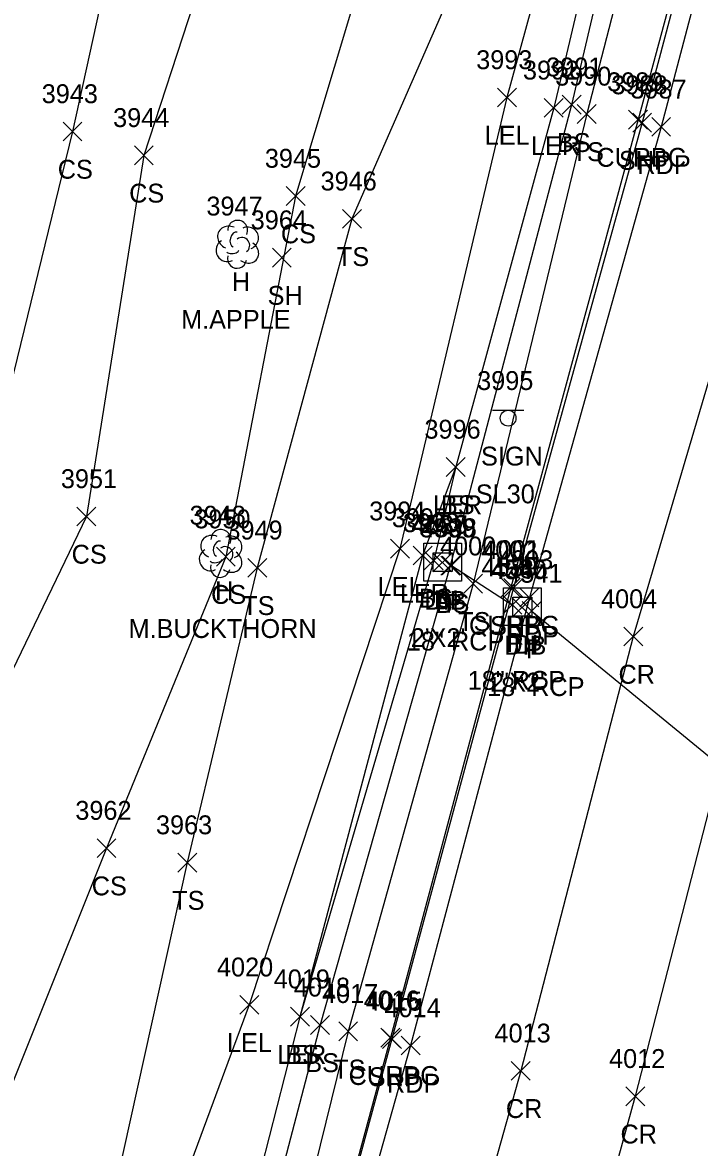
# Model space of a CAD drawing. Extents: x 1462089 to 1464015, y 730534 to 736144.
# Drawn here: x 1462743.8 to 1462815.5, y 732128.7 to 732247.8 of the extents above; entities that cross this region are included whole.
import ezdxf

# ---------------------------------------------------------------- set-up
doc = ezdxf.new("R2010")
doc.units = 0
for name, color, linetype in [('D_A', 7, 'Continuous'), ('D_C', 7, 'Continuous'), ('D_I', 7, 'Continuous'), ('D_TIC', 7, 'Continuous'), ('DCP', 7, 'Continuous'), ('DS', 7, 'Continuous'), ('L_A', 7, 'Continuous'), ('L_C', 7, 'Continuous'), ('L_I', 7, 'Continuous'), ('L_TIC', 7, 'Continuous'), ('LARO', 7, 'Continuous'), ('LELB', 7, 'Continuous'), ('LTD', 7, 'Continuous'), ('P_A', 7, 'Continuous'), ('P_I', 7, 'Continuous'), ('P_TIC', 7, 'Continuous'), ('PET', 7, 'Continuous'), ('PRC', 7, 'Continuous'), ('PSP', 7, 'Continuous'), ('R_A', 7, 'Continuous'), ('R_I', 7, 'Continuous'), ('R_TIC', 7, 'Continuous'), ('RC', 7, 'Continuous'), ('S_A', 7, 'Continuous'), ('S_C', 7, 'Continuous'), ('S_I', 7, 'Continuous'), ('SSGN', 7, 'Continuous')]:
    doc.layers.add(name, color=color, linetype=linetype)

msp = doc.modelspace()

# ---------------------------------------------------------------- linework, layer by layer
at = {"layer": 'D_TIC'}
for points in [[(1462787.24, 732189.65), (1462789.24, 732191.65)], [(1462789.24, 732189.65), (1462787.24, 732191.65)], [(1462788.21, 732189.33), (1462790.21, 732191.33)], [(1462790.21, 732189.33), (1462788.21, 732191.33)], [(1462794.65, 732185.17), (1462796.65, 732187.17)], [(1462796.65, 732185.17), (1462794.65, 732187.17)], [(1462795.69, 732184.89), (1462797.69, 732186.89)], [(1462797.69, 732184.89), (1462795.69, 732186.89)], [(1462796.71, 732184.51), (1462798.71, 732186.51)], [(1462798.71, 732184.51), (1462796.71, 732186.51)]]:
    msp.add_lwpolyline(points, dxfattribs=at)
at = {"layer": 'DCP'}
for points in [[(1462789.21, 732190.33), (1462795.65, 732186.17)], [(1462797.71, 732185.51), (1462855.72, 732137.95)]]:
    msp.add_lwpolyline(points, dxfattribs=at)
at = {"layer": 'DS'}
for p, q in [((1462786.29, 732192.69), (1462790.29, 732192.69)), ((1462786.29, 732188.69), (1462786.29, 732192.69)), ((1462790.29, 732192.69), (1462790.29, 732188.69)), ((1462787.29, 732189.69), (1462787.29, 732191.69)), ((1462787.29, 732191.69), (1462789.29, 732191.69)), ((1462789.29, 732191.69), (1462789.29, 732189.69)), ((1462789.29, 732189.69), (1462787.29, 732189.69)), ((1462788.3, 732190.69), (1462788.3, 732190.69)), ((1462788.3, 732190.69), (1462788.3, 732190.69)), ((1462790.29, 732188.69), (1462786.29, 732188.69)), ((1462794.72, 732187.98), (1462798.72, 732187.98)), ((1462794.72, 732183.98), (1462794.72, 732187.98)), ((1462798.72, 732187.98), (1462798.72, 732183.98)), ((1462795.72, 732184.98), (1462795.72, 732186.98)), ((1462795.72, 732186.98), (1462797.72, 732186.98)), ((1462797.72, 732186.98), (1462797.72, 732184.98)), ((1462797.72, 732184.98), (1462795.72, 732184.98)), ((1462796.72, 732185.98), (1462796.72, 732185.98)), ((1462796.72, 732185.98), (1462796.72, 732185.98)), ((1462798.72, 732183.98), (1462794.72, 732183.98))]:
    msp.add_line(p, q, dxfattribs=at)
at = {"layer": 'L_TIC'}
for points in [[(1462794.09, 732238.9), (1462796.09, 732240.9)], [(1462796.09, 732238.9), (1462794.09, 732240.9)], [(1462799.04, 732237.8), (1462801.04, 732239.8)], [(1462801.04, 732237.8), (1462799.04, 732239.8)], [(1462800.93, 732238.13), (1462802.93, 732240.13)], [(1462802.93, 732238.13), (1462800.93, 732240.13)], [(1462802.53, 732237.16), (1462804.53, 732239.16)], [(1462804.53, 732237.16), (1462802.53, 732239.16)], [(1462748.08, 732235.3), (1462750.08, 732237.3)], [(1462750.08, 732235.3), (1462748.08, 732237.3)], [(1462755.64, 732232.77), (1462757.64, 732234.77)], [(1462757.64, 732232.77), (1462755.64, 732234.77)], [(1462771.71, 732228.46), (1462773.71, 732230.46)], [(1462773.71, 732228.46), (1462771.71, 732230.46)], [(1462777.67, 732226.05), (1462779.67, 732228.05)], [(1462779.67, 732226.05), (1462777.67, 732228.05)], [(1462770.25, 732221.94), (1462772.25, 732223.94)], [(1462772.25, 732221.94), (1462770.25, 732223.94)], [(1462788.66, 732199.77), (1462790.66, 732201.77)], [(1462790.66, 732199.77), (1462788.66, 732201.77)], [(1462788.66, 732199.77), (1462790.66, 732201.77)], [(1462790.66, 732199.77), (1462788.66, 732201.77)], [(1462749.55, 732194.53), (1462751.55, 732196.53)], [(1462751.55, 732194.53), (1462749.55, 732196.53)], [(1462764.32, 732190.27), (1462766.32, 732192.27)], [(1462766.32, 732190.27), (1462764.32, 732192.27)], [(1462782.76, 732191.11), (1462784.76, 732193.11)], [(1462784.76, 732191.11), (1462782.76, 732193.11)], [(1462785.16, 732190.39), (1462787.16, 732192.39)], [(1462787.16, 732190.39), (1462785.16, 732192.39)], [(1462767.65, 732189.09), (1462769.65, 732191.09)], [(1462769.65, 732189.09), (1462767.65, 732191.09)], [(1462786.33, 732189.87), (1462788.33, 732191.87)], [(1462788.33, 732189.87), (1462786.33, 732191.87)], [(1462788.09, 732189.31), (1462790.09, 732191.31)], [(1462790.09, 732189.31), (1462788.09, 732191.31)], [(1462790.51, 732187.4), (1462792.51, 732189.4)], [(1462792.51, 732187.4), (1462790.51, 732189.4)], [(1462751.68, 732159.4), (1462753.68, 732161.4)], [(1462753.68, 732159.4), (1462751.68, 732161.4)], [(1462760.23, 732157.87), (1462762.23, 732159.87)], [(1462762.23, 732157.87), (1462760.23, 732159.87)], [(1462766.8, 732142.81), (1462768.8, 732144.81)], [(1462768.8, 732142.81), (1462766.8, 732144.81)], [(1462772.17, 732141.55), (1462774.17, 732143.55)], [(1462774.17, 732141.55), (1462772.17, 732143.55)], [(1462772.17, 732141.55), (1462774.17, 732143.55)], [(1462774.17, 732141.55), (1462772.17, 732143.55)], [(1462774.29, 732140.68), (1462776.29, 732142.68)], [(1462776.29, 732140.68), (1462774.29, 732142.68)], [(1462777.27, 732140), (1462779.27, 732142)], [(1462779.27, 732140), (1462777.27, 732142)]]:
    msp.add_lwpolyline(points, dxfattribs=at)
at = {"layer": 'LARO'}
for points in [[(1462811.69, 732286.33), (1462807.23, 732269.21), (1462800.04, 732238.8), (1462789.66, 732200.77), (1462786.16, 732191.39), (1462773.17, 732142.55), (1462762.59, 732101.23), (1462750.3, 732056), (1462737.3, 732015), (1462731, 731998.27), (1462722.22, 731986.67), (1462712.54, 731977.49), (1462705.64, 731972.39), (1462692.98, 731969.55), (1462682.24, 731971.77), (1462644.49, 731992.53), (1462610.27, 732008.8), (1462590.7, 732019.88), (1462573.65, 732029.77), (1462532.93, 732051.27)], [(1462803.18, 732269.5), (1462795.09, 732239.9), (1462783.76, 732192.11), (1462767.8, 732143.81), (1462756.83, 732114.21)]]:
    msp.add_lwpolyline(points, dxfattribs=at)
at = {"layer": 'LELB'}
for points in [[(1462595.72, 732406.28), (1462619.4, 732406.7), (1462642.47, 732399.16), (1462667.34, 732396.48), (1462684.1, 732390.5), (1462719.43, 732377.7), (1462729.06, 732369.99), (1462742.49, 732352.09), (1462751.14, 732333.71), (1462745.11, 732312.38), (1462751.49, 732301.01), (1462756.6, 732270.55), (1462749.08, 732236.3), (1462739.5, 732197.27), (1462722.63, 732167.04), (1462705.2, 732121.69), (1462689.78, 732084.32), (1462690.84, 732066.26), (1462684.58, 732060.84), (1462690.56, 732032.44), (1462672.45, 732001.12)], [(1462771.34, 732370.93), (1462788.66, 732351.07), (1462799.07, 732328.54), (1462799.45, 732312.22), (1462793.43, 732294.03), (1462783.04, 732263.92), (1462772.71, 732229.46), (1462765.32, 732191.27), (1462752.68, 732160.4), (1462737.05, 732121.41), (1462720.38, 732070.54)], [(1462809.03, 732269.42), (1462801.93, 732239.13), (1462789.09, 732190.31), (1462775.29, 732141.68), (1462764.64, 732100.96), (1462752.8, 732054.52), (1462739.45, 732014.67), (1462736.17, 731994.63), (1462725.05, 731984.73), (1462716.42, 731972.55), (1462714.31, 731971.44), (1462707, 731968.07), (1462693.67, 731964.39), (1462682.54, 731969.03), (1462671.27, 731974.63), (1462642.39, 731988.79), (1462608.32, 732006.27), (1462574.67, 732024.46), (1462532.58, 732048.41)], [(1462811.59, 732269.3), (1462803.53, 732238.16), (1462791.51, 732188.4), (1462778.27, 732141), (1462768.17, 732100), (1462755.7, 732053.53), (1462741.93, 732013.79), (1462736.19, 731994.54), (1462729.1, 731982.21), (1462724.09, 731974.33), (1462718.35, 731969.42), (1462708.44, 731965.38), (1462694.1, 731962.02), (1462681.52, 731966.68), (1462670.39, 731971.8), (1462640.52, 731985.68), (1462606.11, 732003.49), (1462571.9, 732022.04), (1462531.1, 732045.76)], [(1462767.14, 732265.98), (1462756.64, 732233.77), (1462750.55, 732195.53), (1462735.33, 732163.92), (1462718.25, 732117.57), (1462704.07, 732078.38), (1462702.9, 732059.56), (1462704.25, 732052.77), (1462706.69, 732013.72), (1462698.3, 731996.47), (1462698.4, 731977.76), (1462688.47, 731989.05), (1462672.45, 732001.12), (1462653.69, 732006.74), (1462640.58, 732015.14), (1462615.76, 732028.36), (1462597.06, 732039.34), (1462574.7, 732044.02), (1462549.99, 732062.33), (1462528.92, 732079.24)], [(1462793.48, 732260.93), (1462778.67, 732227.05), (1462768.65, 732190.09), (1462761.23, 732158.87), (1462752.18, 732117.99), (1462746.45, 732098.92), (1462740.89, 732072.95), (1462731.75, 732044.77), (1462721.66, 732011.52), (1462713.9, 731990.4), (1462707.85, 731982.77)], [(1462789.66, 732200.77), (1462787.33, 732190.87), (1462773.17, 732142.55)]]:
    msp.add_lwpolyline(points, dxfattribs=at)
at = {"layer": 'LTD'}
for p, q in [((1462766.52, 732224.4), (1462766.52, 732224.4)), ((1462766.52, 732224.4), (1462766.52, 732224.4)), ((1462764.74, 732191.66), (1462764.74, 732191.66)), ((1462764.74, 732191.66), (1462764.74, 732191.66))]:
    msp.add_line(p, q, dxfattribs=at)
for centre in [(1462766.57, 732225.84), (1462764.79, 732193.1)]:
    msp.add_arc(centre, 1.05, 335.5272, 180.9563, dxfattribs=at)
for centre, major_axis, ratio, start_param, end_param in [((1462765.73, 732225.07), (1.21, -0.51), 0.895232, 1.570796, 4.712389), ((1462766.31, 732224.86), (-0.208, -0.792), 0.645439, 3.141593, 6.283185), ((1462767.56, 732224.99), (-1.14, -0.48), 0.949671, 1.570796, 4.712389), ((1462765.44, 732223.69), (0.58, -1.04), 0.959034, 3.141593, 6.283185), ((1462767.02, 732224.24), (-0.5, 0.667), 0.989748, 3.141593, 6.283185), ((1462767.52, 732223.57), (-1.09, 0.79), 0.841452, 1.570796, 4.712389), ((1462766.52, 732222.9), (0.26, 1.06), 0.942809, 1.570796, 4.712389), ((1462766.06, 732223.65), (-0.625, -0.083), 0.423636, 0, 3.141593), ((1462763.95, 732192.33), (1.21, -0.51), 0.895232, 1.570796, 4.712389), ((1462765.79, 732192.25), (-1.14, -0.48), 0.949671, 1.570796, 4.712389), ((1462763.66, 732190.95), (0.58, -1.04), 0.959034, 3.141593, 6.283185), ((1462764.54, 732192.12), (-0.208, -0.792), 0.645439, 3.141593, 6.283185), ((1462765.24, 732191.5), (-0.5, 0.667), 0.989748, 3.141593, 6.283185), ((1462764.29, 732190.91), (-0.625, -0.083), 0.423636, 0, 3.141593), ((1462765.74, 732190.83), (-1.09, 0.79), 0.841452, 1.570796, 4.712389), ((1462764.74, 732190.16), (0.26, 1.06), 0.942809, 1.570796, 4.712389)]:
    msp.add_ellipse(centre, major_axis=major_axis, ratio=ratio, start_param=start_param, end_param=end_param, dxfattribs=at)
at = {"layer": 'P_TIC'}
for points in [[(1462808.4, 732236.24), (1462810.4, 732238.24)], [(1462810.4, 732236.24), (1462808.4, 732238.24)], [(1462810.42, 732235.79), (1462812.42, 732237.79)], [(1462812.42, 732235.79), (1462810.42, 732237.79)], [(1462794.77, 732186.97), (1462796.77, 732188.97)], [(1462796.77, 732186.97), (1462794.77, 732188.97)], [(1462796.46, 732185.94), (1462798.46, 732187.94)], [(1462798.46, 732185.94), (1462796.46, 732187.94)], [(1462807.46, 732181.81), (1462809.46, 732183.81)], [(1462809.46, 732181.81), (1462807.46, 732183.81)], [(1462781.91, 732139.19), (1462783.91, 732141.19)], [(1462783.91, 732139.19), (1462781.91, 732141.19)], [(1462783.89, 732138.5), (1462785.89, 732140.5)], [(1462785.89, 732138.5), (1462783.89, 732140.5)], [(1462795.54, 732135.82), (1462797.54, 732137.82)], [(1462797.54, 732135.82), (1462795.54, 732137.82)], [(1462807.67, 732133.12), (1462809.67, 732135.12)], [(1462809.67, 732133.12), (1462807.67, 732135.12)]]:
    msp.add_lwpolyline(points, dxfattribs=at)
at = {"layer": 'PET'}
msp.add_lwpolyline([(1462974.36, 732735), (1462957.21, 732680.82), (1462945.36, 732643.96), (1462932.51, 732601.63), (1462920.15, 732563.11), (1462911.43, 732534.97), (1462898.01, 732492.33), (1462884.52, 732450), (1462822.42, 732278.6), (1462811.42, 732236.79), (1462797.46, 732186.94), (1462784.89, 732139.5), (1462773.38, 732098.59), (1462761.09, 732052.78), (1462749.31, 732009.82), (1462737.3, 731963.43), (1462717.1, 731889.53)], dxfattribs=at)
at = {"layer": 'PRC'}
for points in [[(1462985.72, 732731.93), (1462969.44, 732677.27), (1462957.49, 732641.21), (1462943.9, 732597.67), (1462931.65, 732559.61), (1462922.76, 732531.12), (1462910.18, 732489.03), (1462895.07, 732444.4), (1462885.16, 732408.13), (1462864.59, 732375.33), (1462853.42, 732347.26), (1462832.87, 732276.65), (1462823.23, 732232.91), (1462808.46, 732182.81), (1462796.54, 732136.82), (1462784.67, 732094.48), (1462773.76, 732052.9), (1462761.07, 732007.23), (1462748.95, 731961.52), (1462736.51, 731921.31)], [(1462885.16, 732408.13), (1462873.49, 732369.25), (1462865.09, 732342.58), (1462846.12, 732273.83), (1462834.44, 732229.42), (1462820.22, 732178.99), (1462808.67, 732134.12), (1462796.38, 732089.42), (1462785.55, 732047.77), (1462772.99, 732002.51), (1462761.02, 731958.42), (1462747.81, 731917.01)]]:
    msp.add_lwpolyline(points, dxfattribs=at)
at = {"layer": 'PSP'}
msp.add_lwpolyline([(1462968.73, 732736.5), (1462951.61, 732681.88), (1462940.59, 732646.44), (1462927.05, 732603.06), (1462915.13, 732564.78), (1462905.93, 732535.59), (1462892.76, 732493.15), (1462882.84, 732461.98), (1462878.84, 732452.24), (1462860.17, 732402.54), (1462855.98, 732390.47), (1462851.6, 732378.35), (1462831.73, 732320.54), (1462820.54, 732279.17), (1462809.4, 732237.24), (1462795.77, 732187.97), (1462782.91, 732140.19), (1462771.75, 732099.01), (1462759.21, 732053.14), (1462747.62, 732010.5), (1462744.84, 731999.27), (1462735.88, 731965.54), (1462724.35, 731923.62)], dxfattribs=at)
at = {"layer": 'R_TIC'}
for points in [[(1462807.97, 732236.56), (1462809.97, 732238.56)], [(1462809.97, 732236.56), (1462807.97, 732238.56)], [(1462794.49, 732187.01), (1462796.49, 732189.01)], [(1462796.49, 732187.01), (1462794.49, 732189.01)], [(1462781.74, 732139.32), (1462783.74, 732141.32)], [(1462783.74, 732139.32), (1462781.74, 732141.32)]]:
    msp.add_lwpolyline(points, dxfattribs=at)
at = {"layer": 'RC'}
msp.add_lwpolyline([(1462829.93, 732355.37), (1462830.59, 732355.49), (1462831.24, 732353.27), (1462834.24, 732341.28), (1462833.71, 732330.4), (1462831.71, 732320.54), (1462820.1, 732278.81), (1462808.97, 732237.56), (1462795.49, 732188.01), (1462782.74, 732140.32), (1462771.63, 732099.14), (1462759.13, 732053.25), (1462747.5, 732010.47), (1462744.54, 731999.36), (1462742.28, 731993.46), (1462735.21, 731981.65), (1462730.48, 731976.35), (1462728.98, 731974.4)], dxfattribs=at)
at = {"layer": 'SSGN'}
for p, q in [((1462793.56, 732206.77), (1462796.89, 732206.77)), ((1462795.21, 732205.94), (1462795.21, 732205.94))]:
    msp.add_line(p, q, dxfattribs=at)
msp.add_circle((1462795.21, 732205.94), 0.833, dxfattribs=at)

# ---------------------------------------------------------------- texts
at = {"layer": 'D_A'}
for s, p in [('DIB', (1462786.34, 732185.65)), ('DI', (1462787.35, 732185.69)), ('P', (1462788.58, 732185.33)), ('DIB', (1462794.8, 732180.89)), ('P', (1462795.03, 732181.17)), ('DI', (1462795.78, 732180.98)), ('P', (1462797.09, 732180.51))]:
    msp.add_text(s, height=2, dxfattribs=at).set_placement(p)
at = {"layer": 'D_C'}
for s, p in [("2'X2'", (1462784.9, 732181.69)), ('18" RCP', (1462784.49, 732181.33)), ('18" RCP', (1462790.93, 732177.17)), ("2'X2'", (1462793.32, 732176.98)), ('18" RCP', (1462792.99, 732176.51))]:
    msp.add_text(s, height=2, dxfattribs=at).set_placement(p)
at = {"layer": 'D_I'}
for s, p in [('4537', (1462784.98, 732193.65)), ('4536', (1462784.98, 732193.69)), ('4538', (1462785.95, 732193.33)), ('4539', (1462792.38, 732189.17)), ('4540', (1462793.35, 732188.89)), ('4535', (1462793.46, 732188.98)), ('4541', (1462795.01, 732188.51))]:
    msp.add_text(s, height=2, dxfattribs=at).set_placement(p)
at = {"layer": 'L_A'}
for s, p in [('LEL', (1462792.73, 732234.9)), ('BS', (1462800.37, 732234.13)), ('LER', (1462797.62, 732233.8)), ('TS', (1462801.94, 732233.16)), ('CS', (1462747.52, 732231.3)), ('CS', (1462755.08, 732228.77)), ('CS', (1462771.15, 732224.46)), ('TS', (1462777.08, 732222.05)), ('H', (1462765.95, 732219.4)), ('SH', (1462769.74, 732217.94)), ('LER', (1462787.25, 732195.77)), ('BS', (1462788.1, 732195.77)), ('CS', (1462748.99, 732190.53)), ('H', (1462764.18, 732186.66)), ('LEL', (1462781.39, 732187.11)), ('LER', (1462783.74, 732186.39)), ('CS', (1462763.76, 732186.27)), ('BS', (1462785.77, 732185.87)), ('BS', (1462787.54, 732185.31)), ('TS', (1462767.06, 732185.09)), ('TS', (1462789.92, 732183.4)), ('CS', (1462751.12, 732155.4)), ('TS', (1462759.64, 732153.87)), ('LEL', (1462765.44, 732138.81)), ('LER', (1462770.75, 732137.55)), ('BS', (1462771.61, 732137.55)), ('BS', (1462773.73, 732136.68)), ('TS', (1462776.68, 732136))]:
    msp.add_text(s, height=2, dxfattribs=at).set_placement(p)
at = {"layer": 'L_C'}
for s, p in [('M.APPLE', (1462760.58, 732215.4)), ('M.BUCKTHORN', (1462755.02, 732182.66))]:
    msp.add_text(s, height=2, dxfattribs=at).set_placement(p)
at = {"layer": 'L_I'}
for s, p in [('3993', (1462791.83, 732242.9)), ('3992', (1462796.78, 732241.8)), ('3991', (1462799.24, 732242.13)), ('3990', (1462800.19, 732241.16)), ('3943', (1462745.82, 732239.3)), ('3944', (1462753.38, 732236.77)), ('3945', (1462769.45, 732232.46)), ('3946', (1462775.35, 732230.05)), ('3947', (1462763.26, 732227.4)), ('3964', (1462767.95, 732225.94)), ('3996', (1462786.35, 732203.77)), ('3996', (1462786.35, 732203.77)), ('3951', (1462747.85, 732198.53)), ('3994', (1462780.5, 732195.11)), ('3948', (1462761.48, 732194.66)), ('3950', (1462761.98, 732194.27)), ('3997', (1462782.9, 732194.39)), ('3998', (1462784.07, 732193.87)), ('3949', (1462765.38, 732193.09)), ('3999', (1462785.83, 732193.31)), ('4000', (1462788, 732191.4)), ('3962', (1462749.38, 732163.4)), ('3963', (1462757.92, 732161.87)), ('4020', (1462764.38, 732146.81)), ('4019', (1462770.39, 732145.55)), ('4019', (1462770.39, 732145.55)), ('4018', (1462772.52, 732144.68)), ('4017', (1462775.5, 732144))]:
    msp.add_text(s, height=2, dxfattribs=at).set_placement(p)
at = {"layer": 'P_A'}
for s, p in [('SHP', (1462806.94, 732232.24)), ('RDP', (1462808.9, 732231.79)), ('SHP', (1462793.3, 732182.97)), ('RDP', (1462794.95, 732181.94)), ('CR', (1462806.9, 732177.81)), ('SHP', (1462780.45, 732135.19)), ('RDP', (1462782.38, 732134.5)), ('CR', (1462794.97, 732131.82)), ('CR', (1462807.11, 732129.12))]:
    msp.add_text(s, height=2, dxfattribs=at).set_placement(p)
at = {"layer": 'P_I'}
for s, p in [('3988', (1462806.14, 732240.24)), ('3987', (1462808.16, 732239.79)), ('4002', (1462792.35, 732190.97)), ('4003', (1462794.04, 732189.94)), ('4004', (1462805.05, 732185.81)), ('4015', (1462780.14, 732143.19)), ('4014', (1462782.12, 732142.5)), ('4013', (1462793.77, 732139.82)), ('4012', (1462805.9, 732137.12))]:
    msp.add_text(s, height=2, dxfattribs=at).set_placement(p)
at = {"layer": 'R_A'}
for p in [(1462804.55, 732232.56), (1462791.07, 732183.01), (1462778.32, 732135.32)]:
    msp.add_text('CURBC', height=2, dxfattribs=at).set_placement(p)
at = {"layer": 'R_I'}
for s, p in [('3989', (1462805.7, 732240.56)), ('4001', (1462792.64, 732191.01)), ('4016', (1462779.91, 732143.32))]:
    msp.add_text(s, height=2, dxfattribs=at).set_placement(p)
at = {"layer": 'S_A'}
msp.add_text('SIGN', height=2, dxfattribs=at).set_placement((1462792.34, 732200.92))
at = {"layer": 'S_C'}
msp.add_text('SL30', height=2, dxfattribs=at).set_placement((1462791.79, 732196.92))
at = {"layer": 'S_I'}
msp.add_text('3995', height=2, dxfattribs=at).set_placement((1462791.93, 732208.92))

doc.saveas('drawing.dxf')
